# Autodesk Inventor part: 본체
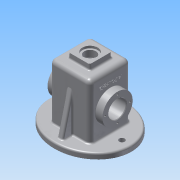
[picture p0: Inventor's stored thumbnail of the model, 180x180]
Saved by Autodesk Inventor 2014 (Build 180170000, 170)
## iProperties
Created: 2017-07
Part Number: 본체
Material: 알루미늄 6061
Document SubType Name: Modeling
Designer: 406-12
Density: 2.71 g/cm^3
Appearance: 알루미늄 - 평지
Mass: 890.222 g
Surface Area: 996.654 cm^2
Volume: 328.495 cm^3
Author: 406-12
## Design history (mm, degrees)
sketch "스케치1"
  geometry: 2 further points; 1 other entity
  constraints: 1 coincident, 2 other
extrude "돌출1" new body sketch "스케치1" distance "d0" = 10; taper "d1" = 0 deg
sketch "스케치2"
  geometry: L1 (0, 10)-(0, 110); L2 (37, 10)-(37, 110); L3 (-37, 10)-(-37, 110); L4 (-74.587, 0)-(99.979, 0); L5 (-37, 110)-(37, 110); L6 (65, 10)-(65, 0) reference; L7 (65, 0)-(-65, 0) reference; L8 (-65, 0)-(-65, 10) reference; L9 (-65, 10)-(65, 10) reference; L10 (-37, 10)-(37, 10); 1 further point
  constraints: 12 end point, 3 parallel, 2 midpoint, 2 point on line
  dimensions: "d2" = 37 distance between parallel lines of L1 L3; "d3" = 37 distance between parallel lines of L2 L1; "d4" = 110 distance between parallel lines of L5 L4
extrude "돌출2" join sketch "스케치2" stored distance "d5" = 74; taper "d6" = 0 deg
sketch "스케치3"
  geometry: L1 (-75, 0)-(-75, 10) reference; L2 (-75, 10)-(-37, 10) reference; L3 (-37, 10)-(-37, 110) reference; L4 (-37, 110)-(37, 110) reference; L5 (37, 110)-(37, 10) reference; L6 (37, 10)-(75, 10) reference; L7 (75, 10)-(75, 0) reference; L8 (75, 0)-(-75, 0) reference; L9 (0, 110)-(0, 120); L10 (-20, 110)-(20, 110); L11 (-19.125, 120)-(19.125, 120); L12 (-20, 110)-(-19.125, 120); L13 (20, 110)-(19.125, 120); 3 further points
  constraints: 10 end point, 2 midpoint, 1 parallel, 1 symmetric about line
  dimensions: "d9" = 10 distance between parallel lines of L4 L11; "d13" = 5 deg angle of L12 L3
extrude "돌출3" join sketch "스케치3" stored distance "d14" = 40; taper "d15" = 0 deg
sketch "스케치4"
  geometry: L1 (-75, 0)-(-75, 10) reference; L2 (-75, 10)-(-37, 10) reference; L3 (-37, 10)-(-37, 110) reference; L4 (-37, 110)-(-20, 110) reference; L5 (-20, 110)-(-19.125, 120) reference; L6 (-19.125, 120)-(19.125, 120) reference; L7 (19.125, 120)-(20, 110) reference; L8 (20, 110)-(37, 110) reference; L9 (37, 110)-(37, 10) reference; L10 (37, 10)-(75, 10) reference; L11 (75, 10)-(75, 0) reference; L12 (75, 0)-(-75, 0) reference; L13 (-32, 0)-(32, 0); L14 (-32, 0)-(-32, 105); L15 (0, 0)-(0, 105); L16 (32, 0)-(32, 105); L17 (-32, 105)-(32, 105); L18 (-32, 0)-(32, 0)
  constraints: 12 end point, 3 parallel, 1 midpoint
extrude "돌출4" cut sketch "스케치4" stored distance "d19" = 64; taper "d20" = 0 deg
node "작업 평면1"
sketch "스케치7"
  geometry: L1 (-10, 48.448)-(0, 48.448) reference; L2 (0, 48.448)-(0, -48.448) reference; L3 (0, -48.448)-(-10, -48.448) reference; L4 (-10, -48.448)-(-10, 48.448) reference; L5 (0, 0)-(-55, 0); C1 r 27.5 at (-55, 0)
  constraints: 2 end point, 1 centre point, 1 coincident
extrude "돌출5" join sketch "스케치7" stored distance "d22" = 64; taper "d23" = 0 deg
sketch "스케치8"
  geometry: L1 (0, 32)-(55, 32); C1 r 27.5 at (55, 32)
  constraints: 2 end point, 1 centre point, 1 coincident
extrude "돌출6" join sketch "스케치8" distance "d24" = 7; taper "d25" = 0 deg
chamfer "모따기1" distance "d26" = 7; stored, may be unused: second distance "d27" = 2, angle "d28" = 135 deg
hole "구멍1" diameter "d31" = 32; stored, may be unused: countersink angle "d35" = 90 deg, drill point angle "d37" = 0 deg; dims "d29" = 10, "d30" = 10, "d32" = 6, "d33" = 4, "d34" = 2, "d36" = 25
sketch "스케치10"
  geometry: 5 further points
hole "구멍2" sketch "스케치10" at (-22.5, 0), (0, -22.5), (22.5, 0), (0, 22.5) diameter "d38" = 3.242; stored, may be unused: countersink angle "d42" = 90 deg, drill point angle "d44" = 118 deg; dims "d39" = 8, "d40" = 4, "d41" = 2, "d43" = 10
sketch "스케치11"
  geometry: 1 further point
hole "구멍3" sketch "스케치11" at (19.125, -20) diameter "d45" = 21; stored, may be unused: countersink angle "d49" = 90 deg, drill point angle "d51" = 118 deg; dims "d46" = 8, "d47" = 28, "d48" = 4, "d50" = 25
sketch "스케치12"
  geometry: L1 (-65, 10)-(-65, 0) reference; L2 (-65, 0)-(-32, 0) reference; L3 (-32, 0)-(-32, 105) reference; L4 (-32, 105)-(-10.5, 105) reference; L5 (-10.5, 105)-(-10.5, 116) reference; L6 (-10.5, 116)-(-14, 116) reference; L7 (-14, 116)-(-14, 120) reference; L8 (-14, 120)-(-20, 120) reference; L9 (-20, 120)-(-20, 110) reference; L10 (-20, 110)-(-37, 110) reference; L11 (-37, 110)-(-37, 10) reference; L12 (-37, 10)-(-65, 10) reference; L13 (65, 0)-(65, 10) reference; L14 (65, 10)-(37, 10) reference; L15 (37, 10)-(37, 110) reference; L16 (37, 110)-(20, 110) reference; L17 (20, 110)-(20, 120) reference; L18 (20, 120)-(14, 120) reference; L19 (14, 120)-(14, 116) reference; L20 (14, 116)-(10.5, 116) reference; L21 (10.5, 116)-(10.5, 105) reference; L22 (10.5, 105)-(32, 105) reference; L23 (32, 105)-(32, 0) reference; L24 (32, 0)-(65, 0) reference; L25 (-65, 0)-(-65, 22.039); L26 (-55, 10)-(-37, 82.194); L27 (-55, 10)-(-37, 10); L28 (-37, 10)-(-37, 82.194); 1 further point
  constraints: 8 end point, 2 point on line
  dimensions: "d54" = 14 deg angle of L1 L26
extrude "돌출7" join sketch "스케치12" stored distance "d55" = 10; taper "d56" = 0 deg
sketch "스케치13"
  geometry: L1 (-10, -56.54)-(-10, -37) reference; L2 (-10, -37)-(-10, 37) reference; L3 (-10, 37)-(-10, 56.54) reference; L4 (-10, 56.54)-(0, 56.54) reference; L5 (0, 56.54)-(0, -56.54) reference; L6 (0, -56.54)-(-10, -56.54) reference; L7 (-10, -37)-(-110, -37) reference; L8 (-110, -37)-(-110, 37) reference; L9 (-110, 37)-(-10, 37) reference; L10 (-110, -20)-(-120, -20) reference; L11 (-120, 20)-(-110, 20) reference; C1 r 16 at (-55, 0) reference; C2 r 27.5 at (-55, 0) reference; 2 further points
  constraints: 1 other
feature "엠보싱1" sketch "스케치13" dims "d1" = 0, "d58" = 0.5, "d59" = 0
fillet "모깎기1" dims "d60" = 8
fillet "모깎기2" dims "d61" = 8
fillet "모깎기3" dims "d62" = 0.5
fillet "모깎기4" dims "d63" = 0.5
chamfer "모따기2" distance "d64" = 1; stored, may be unused: second distance "d65" = 2, angle "d66" = 135 deg
fillet "모깎기5" dims "d67" = 3
fillet "모깎기6" dims "d68" = 3
fillet "모깎기7" dims "d69" = 3
fillet "모깎기8" dims "d70" = 3
fillet "모깎기9" dims "d71" = 3
fillet "모깎기10" dims "d72" = 3
sketch "스케치14"
  geometry: L1 (0, -65)-(0, 103.322); L2 (-58, -72.269)-(-58, 103.322); L3 (58, -72.269)-(58, 103.322); 3 further points; 1 other entity
  constraints: 6 end point, 2 parallel, 2 point on line, 1 vertical alignment, 1 other
  dimensions: "d73" = 58 distance between parallel lines of L2 L1; "d74" = 58 distance between parallel lines of L3 L1
hole "구멍4" sketch "스케치14" at (-58, 0), (58, 0) diameter "d75" = 10; stored, may be unused: countersink angle "d79" = 90 deg, drill point angle "d81" = 118 deg; dims "d76" = 8, "d77" = 4, "d78" = 2, "d80" = 25
fillet "모깎기11" dims "d82" = 3
node "솔리드1"
mirror "대칭1"
mirror "대칭2"
node "작업 평면2"
node "작업 평면3"
node "절단 모서리 투영1"
node "절단 모서리 투영2"
node "절단 모서리 투영3"
node "절단 모서리 투영4"
node "절단 모서리 투영5"
node "절단 모서리 투영6"
other parameters: "d16" = 32, "d17" = 32, "d18" = 105, "d21" = 13
